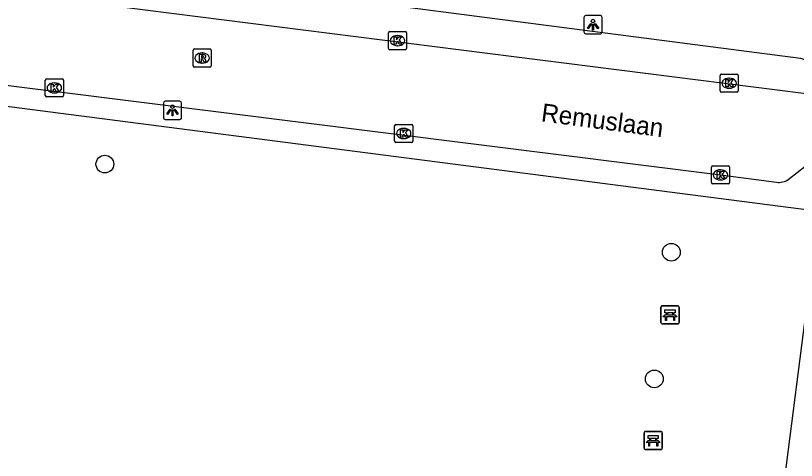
# Model space of a CAD drawing. Extents: x 162186 to 163152, y 385513 to 386513.
# Drawn here: x 162402.52 to 162445.59, y 386238.09 to 386262.59 of the extents above; entities that cross this region are included whole.
import ezdxf

# ---------------------------------------------------------------- set-up
doc = ezdxf.new("R2010")
doc.units = 0
for name, color, linetype in [('IMGEO_Bank', 7, 'Continuous'), ('IMGEO_Boom', 7, 'Continuous'), ('IMGEO_Kolk', 7, 'Continuous'), ('IMGEO_Lichtpunt', 7, 'Continuous'), ('IMGEO_Openbare_ruimte_label', 7, 'Continuous'), ('IMGEO_Rijbaan_lokaal_open', 7, 'Continuous'), ('IMGEO_Rioolput', 7, 'Continuous'), ('IMGEO_Voetpad_open', 7, 'Continuous')]:
    doc.layers.add(name, color=color, linetype=linetype)

msp = doc.modelspace()

# ---------------------------------------------------------------- linework, layer by layer
at = {"layer": 'IMGEO_Bank'}
for p, q in [((162438.12, 386245.681), (162438.12, 386246.522)), ((162438.12, 386246.522), (162438.12, 386245.681)), ((162438.195, 386246.606), (162439.036, 386246.606)), ((162439.036, 386246.606), (162438.195, 386246.606)), ((162439.12, 386246.531), (162439.12, 386245.69)), ((162439.12, 386245.69), (162439.12, 386246.531)), ((162438.817, 386246.004), (162438.424, 386246.004)), ((162438.429, 386246.112), (162438.429, 386246.218)), ((162438.473, 386246.218), (162438.473, 386246.112)), ((162438.761, 386246.224), (162438.479, 386246.224)), ((162438.479, 386246.106), (162438.761, 386246.106)), ((162438.767, 386246.112), (162438.767, 386246.218)), ((162438.811, 386246.218), (162438.811, 386246.112)), ((162439.045, 386245.606), (162438.204, 386245.606)), ((162438.204, 386245.606), (162439.045, 386245.606)), ((162437.192, 386238.751), (162437.192, 386239.592)), ((162437.192, 386239.592), (162437.192, 386238.751)), ((162437.267, 386239.676), (162438.108, 386239.676)), ((162438.108, 386239.676), (162437.267, 386239.676)), ((162438.192, 386239.601), (162438.192, 386238.76)), ((162438.192, 386238.76), (162438.192, 386239.601)), ((162437.889, 386239.074), (162437.496, 386239.074)), ((162437.501, 386239.182), (162437.501, 386239.288)), ((162437.545, 386239.288), (162437.545, 386239.182)), ((162437.833, 386239.294), (162437.551, 386239.294)), ((162437.551, 386239.176), (162437.833, 386239.176)), ((162437.839, 386239.182), (162437.839, 386239.288)), ((162437.883, 386239.288), (162437.883, 386239.182)), ((162438.117, 386238.676), (162437.276, 386238.676)), ((162437.276, 386238.676), (162438.117, 386238.676))]:
    msp.add_line(p, q, dxfattribs=at)
for points in [[(162438.423, 386246.224), (162438.337, 386246.224), (162438.337, 386246.385), (162438.9, 386246.385), (162438.9, 386246.224), (162438.817, 386246.224)], [(162438.367, 386246.004), (162438.225, 386246.004), (162438.337, 386246.106), (162438.423, 386246.106)], [(162438.417, 386245.997), (162438.417, 386245.79), (162438.374, 386245.79), (162438.374, 386245.997)], [(162438.817, 386246.106), (162438.9, 386246.106), (162439.012, 386246.004), (162438.873, 386246.004)], [(162438.867, 386245.997), (162438.867, 386245.79), (162438.823, 386245.79), (162438.823, 386245.997)], [(162437.439, 386239.074), (162437.297, 386239.074), (162437.409, 386239.176), (162437.495, 386239.176)], [(162437.495, 386239.294), (162437.409, 386239.294), (162437.409, 386239.455), (162437.972, 386239.455), (162437.972, 386239.294), (162437.889, 386239.294)], [(162437.489, 386239.067), (162437.489, 386238.86), (162437.446, 386238.86), (162437.446, 386239.067)], [(162437.889, 386239.176), (162437.972, 386239.176), (162438.084, 386239.074), (162437.945, 386239.074)], [(162437.939, 386239.067), (162437.939, 386238.86), (162437.895, 386238.86), (162437.895, 386239.067)]]:
    msp.add_lwpolyline(points, dxfattribs=at)
for centre, radius, start, end in [((162438.198, 386246.528), 0.0779, 92.4484, 184.2845), ((162438.198, 386246.528), 0.0779, 92.4484, 184.2845), ((162439.042, 386246.528), 0.0779, 2.4484, 94.2845), ((162439.042, 386246.528), 0.0779, 2.4484, 94.2845), ((162438.367, 386245.997), 0.00671, 2.8957, 87.1043), ((162438.424, 386245.997), 0.00671, 92.8957, 177.1043), ((162438.422, 386246.217), 0.00671, 2.8957, 87.1043), ((162438.422, 386246.113), 0.00671, 272.8957, 357.1043), ((162438.479, 386246.217), 0.00671, 92.8957, 177.1043), ((162438.479, 386246.113), 0.00671, 182.8957, 267.1043), ((162438.761, 386246.217), 0.00671, 2.8957, 87.1043), ((162438.761, 386246.113), 0.00671, 272.8957, 357.1043), ((162438.818, 386246.217), 0.00671, 92.8957, 177.1043), ((162438.818, 386246.113), 0.00671, 182.8957, 267.1043), ((162438.816, 386245.997), 0.00671, 2.8957, 87.1043), ((162438.873, 386245.997), 0.00671, 92.8957, 177.1043), ((162438.198, 386245.684), 0.0779, 182.4484, 274.2845), ((162438.198, 386245.684), 0.0779, 182.4484, 274.2845), ((162439.042, 386245.684), 0.0779, 272.4484, 4.2845), ((162439.042, 386245.684), 0.0779, 272.4484, 4.2845), ((162437.27, 386239.598), 0.0779, 92.4484, 184.2845), ((162437.27, 386239.598), 0.0779, 92.4484, 184.2845), ((162438.114, 386239.598), 0.0779, 2.4484, 94.2845), ((162438.114, 386239.598), 0.0779, 2.4484, 94.2845), ((162437.439, 386239.067), 0.00671, 2.8957, 87.1043), ((162437.496, 386239.067), 0.00671, 92.8957, 177.1043), ((162437.494, 386239.287), 0.00671, 2.8957, 87.1043), ((162437.494, 386239.183), 0.00671, 272.8957, 357.1043), ((162437.551, 386239.287), 0.00671, 92.8957, 177.1043), ((162437.551, 386239.183), 0.00671, 182.8957, 267.1043), ((162437.833, 386239.287), 0.00671, 2.8957, 87.1043), ((162437.833, 386239.183), 0.00671, 272.8957, 357.1043), ((162437.89, 386239.287), 0.00671, 92.8957, 177.1043), ((162437.89, 386239.183), 0.00671, 182.8957, 267.1043), ((162437.888, 386239.067), 0.00671, 2.8957, 87.1043), ((162437.945, 386239.067), 0.00671, 92.8957, 177.1043), ((162437.27, 386238.754), 0.0779, 182.4484, 274.2845), ((162437.27, 386238.754), 0.0779, 182.4484, 274.2845), ((162438.114, 386238.754), 0.0779, 272.4484, 4.2845), ((162438.114, 386238.754), 0.0779, 272.4484, 4.2845)]:
    msp.add_arc(centre, radius, start, end, dxfattribs=at)
at = {"layer": 'IMGEO_Boom'}
for centre in [(162407.446, 386254.411), (162438.692, 386249.555), (162437.754, 386242.576)]:
    msp.add_circle(centre, 0.489, dxfattribs=at)
at = {"layer": 'IMGEO_Kolk'}
for p, q in [((162423.091, 386260.791), (162423.091, 386261.643)), ((162423.166, 386261.717), (162424.018, 386261.717)), ((162423.579, 386261.497), (162423.604, 386261.497)), ((162424.092, 386261.643), (162424.092, 386260.791)), ((162424.018, 386260.717), (162423.166, 386260.717)), ((162423.602, 386260.937), (162423.577, 386260.937)), ((162441.383, 386258.442), (162441.383, 386259.294)), ((162441.458, 386259.368), (162442.31, 386259.368)), ((162442.384, 386259.294), (162442.384, 386258.442)), ((162404.16, 386258.185), (162404.16, 386259.037)), ((162404.235, 386259.111), (162405.087, 386259.111)), ((162404.648, 386258.891), (162404.673, 386258.891)), ((162405.161, 386259.037), (162405.161, 386258.185)), ((162441.871, 386259.148), (162441.896, 386259.148)), ((162441.894, 386258.588), (162441.869, 386258.588)), ((162405.087, 386258.111), (162404.235, 386258.111)), ((162404.671, 386258.331), (162404.646, 386258.331)), ((162442.31, 386258.368), (162441.458, 386258.368)), ((162423.43, 386255.675), (162423.43, 386256.527)), ((162423.505, 386256.601), (162424.357, 386256.601)), ((162423.918, 386256.381), (162423.943, 386256.381)), ((162424.431, 386256.527), (162424.431, 386255.675)), ((162424.357, 386255.601), (162423.505, 386255.601)), ((162423.941, 386255.821), (162423.916, 386255.821)), ((162440.901, 386253.391), (162440.901, 386254.243)), ((162440.976, 386254.317), (162441.828, 386254.317)), ((162441.902, 386254.243), (162441.902, 386253.391)), ((162441.389, 386254.097), (162441.414, 386254.097)), ((162441.828, 386253.317), (162440.976, 386253.317)), ((162441.412, 386253.537), (162441.387, 386253.537))]:
    msp.add_line(p, q, dxfattribs=at)
for points in [[(162423.091, 386260.791), (162423.091, 386261.643)], [(162423.166, 386261.717), (162424.018, 386261.717)], [(162424.092, 386261.643), (162424.092, 386260.791)], [(162423.412, 386261.417), (162423.535, 386261.417), (162423.535, 386261.266), (162423.665, 386261.417), (162423.829, 386261.417), (162423.683, 386261.266), (162423.836, 386261.017), (162423.684, 386261.017), (162423.599, 386261.181), (162423.535, 386261.114), (162423.535, 386261.017), (162423.412, 386261.017), (162423.412, 386261.417)], [(162424.018, 386260.717), (162423.166, 386260.717)], [(162441.383, 386258.442), (162441.383, 386259.294)], [(162441.458, 386259.368), (162442.31, 386259.368)], [(162442.384, 386259.294), (162442.384, 386258.442)], [(162404.16, 386258.185), (162404.16, 386259.037)], [(162404.235, 386259.111), (162405.087, 386259.111)], [(162405.161, 386259.037), (162405.161, 386258.185)], [(162441.704, 386259.068), (162441.827, 386259.068), (162441.827, 386258.917), (162441.957, 386259.068), (162442.121, 386259.068), (162441.975, 386258.917), (162442.128, 386258.668), (162441.976, 386258.668), (162441.891, 386258.832), (162441.827, 386258.765), (162441.827, 386258.668), (162441.704, 386258.668), (162441.704, 386259.068)], [(162404.481, 386258.811), (162404.604, 386258.811), (162404.604, 386258.66), (162404.734, 386258.811), (162404.898, 386258.811), (162404.752, 386258.66), (162404.905, 386258.411), (162404.753, 386258.411), (162404.668, 386258.575), (162404.604, 386258.508), (162404.604, 386258.411), (162404.481, 386258.411), (162404.481, 386258.811)], [(162405.087, 386258.111), (162404.235, 386258.111)], [(162442.31, 386258.368), (162441.458, 386258.368)], [(162423.43, 386255.675), (162423.43, 386256.527)], [(162423.505, 386256.601), (162424.357, 386256.601)], [(162423.751, 386256.301), (162423.874, 386256.301), (162423.874, 386256.15), (162424.004, 386256.301), (162424.168, 386256.301), (162424.022, 386256.15), (162424.175, 386255.901), (162424.023, 386255.901), (162423.938, 386256.065), (162423.874, 386255.998), (162423.874, 386255.901), (162423.751, 386255.901), (162423.751, 386256.301)], [(162424.431, 386256.527), (162424.431, 386255.675)], [(162424.357, 386255.601), (162423.505, 386255.601)], [(162440.901, 386253.391), (162440.901, 386254.243)], [(162440.976, 386254.317), (162441.828, 386254.317)], [(162441.902, 386254.243), (162441.902, 386253.391)], [(162441.222, 386254.017), (162441.345, 386254.017), (162441.345, 386253.866), (162441.475, 386254.017), (162441.639, 386254.017), (162441.493, 386253.866), (162441.646, 386253.617), (162441.494, 386253.617), (162441.409, 386253.781), (162441.345, 386253.714), (162441.345, 386253.617), (162441.222, 386253.617), (162441.222, 386254.017)], [(162441.828, 386253.317), (162440.976, 386253.317)]]:
    msp.add_lwpolyline(points, dxfattribs=at)
for centre, start, end in [((162423.168, 386261.641), 91.552, 178.448), ((162423.168, 386261.641), 91.552, 178.448), ((162424.016, 386261.641), 1.552, 88.448), ((162424.016, 386261.641), 1.552, 88.448), ((162423.168, 386260.793), 181.552, 268.448), ((162423.168, 386260.793), 181.552, 268.448), ((162424.016, 386260.793), 271.552, 358.448), ((162424.016, 386260.793), 271.552, 358.448), ((162441.46, 386259.292), 91.552, 178.448), ((162441.46, 386259.292), 91.552, 178.448), ((162442.308, 386259.292), 1.552, 88.448), ((162442.308, 386259.292), 1.552, 88.448), ((162404.237, 386259.035), 91.552, 178.448), ((162404.237, 386259.035), 91.552, 178.448), ((162405.085, 386259.035), 1.552, 88.448), ((162405.085, 386259.035), 1.552, 88.448), ((162441.46, 386258.444), 181.552, 268.448), ((162441.46, 386258.444), 181.552, 268.448), ((162442.308, 386258.444), 271.552, 358.448), ((162442.308, 386258.444), 271.552, 358.448), ((162404.237, 386258.187), 181.552, 268.448), ((162404.237, 386258.187), 181.552, 268.448), ((162405.085, 386258.187), 271.552, 358.448), ((162405.085, 386258.187), 271.552, 358.448), ((162423.507, 386256.525), 91.552, 178.448), ((162423.507, 386256.525), 91.552, 178.448), ((162424.355, 386256.525), 1.552, 88.448), ((162424.355, 386256.525), 1.552, 88.448), ((162423.507, 386255.677), 181.552, 268.448), ((162423.507, 386255.677), 181.552, 268.448), ((162424.355, 386255.677), 271.552, 358.448), ((162424.355, 386255.677), 271.552, 358.448), ((162440.978, 386254.241), 91.552, 178.448), ((162440.978, 386254.241), 91.552, 178.448), ((162441.826, 386254.241), 1.552, 88.448), ((162441.826, 386254.241), 1.552, 88.448), ((162440.978, 386253.393), 181.552, 268.448), ((162440.978, 386253.393), 181.552, 268.448), ((162441.826, 386253.393), 271.552, 358.448), ((162441.826, 386253.393), 271.552, 358.448)]:
    msp.add_arc(centre, 0.0765, start, end, dxfattribs=at)
for centre, major_axis, ratio, start_param, end_param in [((162423.578, 386261.217), (-0.387, 0.002), 0.722429, 4.712389, 7.853982), ((162423.603, 386261.217), (-0.39, 0.002), 0.717154, 1.570796, 4.712389), ((162404.647, 386258.611), (-0.387, 0.002), 0.722429, 4.712389, 7.853982), ((162404.672, 386258.611), (-0.39, 0.002), 0.717154, 1.570796, 4.712389), ((162441.87, 386258.868), (-0.387, 0.002), 0.722429, 4.712389, 7.853982), ((162441.895, 386258.868), (-0.39, 0.002), 0.717154, 1.570796, 4.712389), ((162423.917, 386256.101), (-0.387, 0.002), 0.722429, 4.712389, 7.853982), ((162423.942, 386256.101), (-0.39, 0.002), 0.717154, 1.570796, 4.712389), ((162441.388, 386253.817), (-0.387, 0.002), 0.722429, 4.712389, 7.853982), ((162441.413, 386253.817), (-0.39, 0.002), 0.717154, 1.570796, 4.712389)]:
    msp.add_ellipse(centre, major_axis=major_axis, ratio=ratio, start_param=start_param, end_param=end_param, dxfattribs=at)
at = {"layer": 'IMGEO_Lichtpunt'}
for p, q in [((162433.875, 386262.499), (162433.875, 386261.692)), ((162433.875, 386262.499), (162433.875, 386261.692)), ((162434.777, 386262.594), (162433.969, 386262.594)), ((162434.777, 386262.594), (162433.969, 386262.594)), ((162434.871, 386261.692), (162434.871, 386262.499)), ((162434.871, 386261.692), (162434.871, 386262.499)), ((162433.969, 386261.598), (162434.777, 386261.598)), ((162433.969, 386261.598), (162434.777, 386261.598)), ((162410.68, 386257.778), (162410.68, 386256.971)), ((162410.68, 386257.778), (162410.68, 386256.971)), ((162411.582, 386257.873), (162410.774, 386257.873)), ((162411.582, 386257.873), (162410.774, 386257.873)), ((162411.676, 386256.971), (162411.676, 386257.778)), ((162411.676, 386256.971), (162411.676, 386257.778)), ((162410.774, 386256.877), (162411.582, 386256.877)), ((162410.774, 386256.877), (162411.582, 386256.877))]:
    msp.add_line(p, q, dxfattribs=at)
for points in [[(162434.249, 386262.163), (162434.288, 386262.135), (162434.1, 386261.873), (162434.062, 386261.9), (162434.249, 386262.163)], [(162434.351, 386262.115), (162434.398, 386262.115), (162434.398, 386261.793), (162434.351, 386261.793), (162434.351, 386262.115)], [(162434.461, 386262.135), (162434.499, 386262.162), (162434.686, 386261.9), (162434.647, 386261.872), (162434.461, 386262.135)], [(162411.054, 386257.442), (162411.093, 386257.414), (162410.905, 386257.152), (162410.867, 386257.179), (162411.054, 386257.442)], [(162411.156, 386257.394), (162411.203, 386257.394), (162411.203, 386257.072), (162411.156, 386257.072), (162411.156, 386257.394)], [(162411.266, 386257.414), (162411.304, 386257.441), (162411.491, 386257.179), (162411.452, 386257.151), (162411.266, 386257.414)]]:
    msp.add_lwpolyline(points, dxfattribs=at)
for centre in [(162434.374, 386262.297), (162411.179, 386257.576)]:
    msp.add_circle(centre, 0.0994, dxfattribs=at)
for centre, start, end in [((162433.969, 386262.499), 90, 180), ((162433.969, 386262.499), 90, 180), ((162434.777, 386262.499), 0, 90), ((162434.777, 386262.499), 0, 90), ((162433.969, 386261.692), 180, 270), ((162433.969, 386261.692), 180, 270), ((162434.777, 386261.692), 270, 0), ((162434.777, 386261.692), 270, 360), ((162410.774, 386257.778), 90, 180), ((162410.774, 386257.778), 90, 180), ((162411.582, 386257.778), 0, 90), ((162411.582, 386257.778), 0, 90), ((162410.774, 386256.971), 180, 270), ((162410.774, 386256.971), 180, 270), ((162411.582, 386256.971), 270, 0), ((162411.582, 386256.971), 270, 360)]:
    msp.add_arc(centre, 0.0946, start, end, dxfattribs=at)
at = {"layer": 'IMGEO_Rijbaan_lokaal_open'}
for points in [[(162448.882, 386257.938), (162386.418, 386265.855)], [(162381.763, 386261.292), (162441.402, 386253.817), (162444.495, 386253.412), (162444.58, 386253.405), (162444.664, 386253.405), (162444.749, 386253.412), (162444.832, 386253.427), (162444.914, 386253.45), (162444.994, 386253.48), (162445.07, 386253.517), (162445.143, 386253.56), (162445.213, 386253.611), (162446.476, 386254.607), (162446.599, 386254.696), (162446.743, 386254.783), (162446.893, 386254.857), (162447.05, 386254.916), (162447.212, 386254.962), (162447.377, 386254.993), (162447.544, 386255.009), (162447.712, 386255.01), (162447.879, 386254.996), (162448.543, 386254.91)]]:
    msp.add_lwpolyline(points, dxfattribs=at)
at = {"layer": 'IMGEO_Rioolput'}
for p, q in [((162412.317, 386259.83), (162412.317, 386260.682)), ((162412.392, 386260.756), (162413.244, 386260.756)), ((162413.318, 386260.682), (162413.318, 386259.83)), ((162412.805, 386260.536), (162412.83, 386260.536)), ((162413.244, 386259.756), (162412.392, 386259.756)), ((162412.828, 386259.976), (162412.803, 386259.976))]:
    msp.add_line(p, q, dxfattribs=at)
for points in [[(162412.317, 386259.83), (162412.317, 386260.682)], [(162412.392, 386260.756), (162413.244, 386260.756)], [(162413.318, 386260.682), (162413.318, 386259.83)], [(162412.906, 386260.454), (162412.654, 386260.456), (162412.654, 386260.056)], [(162412.654, 386260.056), (162412.778, 386260.056), (162412.778, 386260.218), (162412.789, 386260.218)], [(162412.832, 386260.375), (162412.778, 386260.375), (162412.778, 386260.294)], [(162412.778, 386260.294), (162412.83, 386260.294)], [(162412.836, 386260.189), (162412.907, 386260.056), (162413.047, 386260.056), (162412.982, 386260.182)], [(162413.244, 386259.756), (162412.392, 386259.756)]]:
    msp.add_lwpolyline(points, dxfattribs=at)
for centre, radius, start, end in [((162412.394, 386260.68), 0.0765, 91.552, 178.448), ((162412.394, 386260.68), 0.0765, 91.552, 178.448), ((162413.242, 386260.68), 0.0765, 1.552, 88.448), ((162413.242, 386260.68), 0.0765, 1.552, 88.448), ((162412.788, 386260.165), 0.0533, 26.0293, 88.6989), ((162412.814, 386260.483), 0.19, 274.7715, 282.9687), ((162412.838, 386260.279), 0.0964, 77.0061, 93.1865), ((162412.852, 386260.336), 0.0378, 276.6634, 79.6772), ((162412.905, 386260.344), 0.109, 350.3612, 89.416), ((162412.903, 386260.344), 0.112, 277.5842, 350.9817), ((162412.887, 386260.129), 0.108, 29.5134, 73.7905), ((162412.394, 386259.832), 0.0765, 181.552, 268.448), ((162412.394, 386259.832), 0.0765, 181.552, 268.448), ((162413.242, 386259.832), 0.0765, 271.552, 358.448), ((162413.242, 386259.832), 0.0765, 271.552, 358.448)]:
    msp.add_arc(centre, radius, start, end, dxfattribs=at)
for centre, major_axis, ratio, start_param, end_param in [((162412.804, 386260.256), (-0.387, 0.002), 0.722429, 4.712389, 7.853982), ((162412.829, 386260.256), (-0.39, 0.002), 0.717154, 1.570796, 4.712389)]:
    msp.add_ellipse(centre, major_axis=major_axis, ratio=ratio, start_param=start_param, end_param=end_param, dxfattribs=at)
at = {"layer": 'IMGEO_Voetpad_open'}
for points in [[(162405.863, 386265.443), (162445.81, 386260.241), (162446.232, 386260.105), (162446.358, 386260.037), (162446.458, 386259.984), (162446.794, 386259.589), (162447.449, 386258.809)], [(162446.843, 386251.794), (162383.232, 386260.004)], [(162444.246, 386231.665), (162446.611, 386250), (162446.843, 386251.794)]]:
    msp.add_lwpolyline(points, dxfattribs=at)

# ---------------------------------------------------------------- texts
at = {"layer": 'IMGEO_Openbare_ruimte_label'}
msp.add_text('Remuslaan', height=1, rotation=352.534, dxfattribs=at).set_placement((162431.477, 386256.774))

doc.saveas('drawing.dxf')
